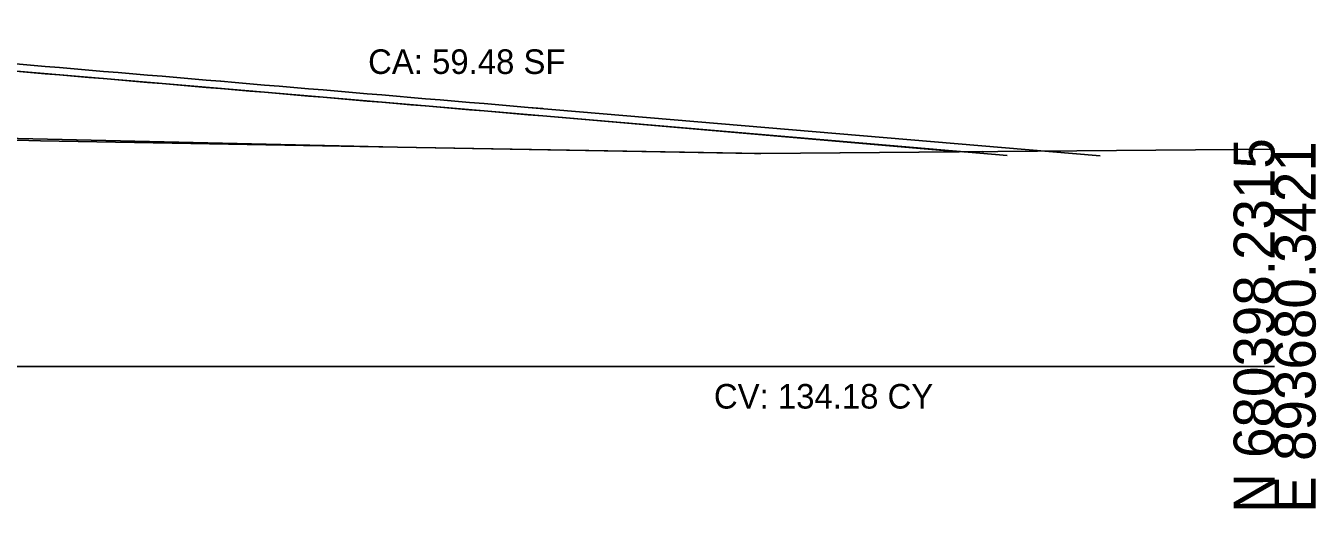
# Model space of a CAD drawing. Extents: x -26 to 4303, y -13 to 10775.
# Drawn here: x 1214.7 to 1302.8, y 490.3 to 523.3 of the extents above; entities that cross this region are included whole.
import ezdxf

# ---------------------------------------------------------------- set-up
doc = ezdxf.new("R2010")
doc.units = 0
for name, color, linetype in [('DTM_P_FINISHED_GRADE', 7, 'Continuous'), ('DTM_X_GROUND', 7, 'Continuous'), ('X_PROFILES_1', 7, 'Continuous'), ('XS_CELL', 7, 'Continuous'), ('XS_M_SHAPES_EARTHWORK', 7, 'Continuous'), ('XS_P_DR_GRAVEL', 7, 'Continuous'), ('XS_SHEET_EW_TX_AREA', 7, 'Continuous'), ('XS_SHEET_EW_TX_VOLUME', 7, 'Continuous')]:
    doc.layers.add(name, color=color, linetype=linetype)

msp = doc.modelspace()

# ---------------------------------------------------------------- linework, layer by layer
at = {"layer": 'DTM_P_FINISHED_GRADE'}
for p, q in [((1214.001, 520.688), (1215.001, 520.603)), ((1215.001, 520.603), (1216.001, 520.518)), ((1216.001, 520.518), (1216.001, 520.518)), ((1216.001, 520.518), (1217.001, 520.433)), ((1217.001, 520.433), (1217.001, 520.433)), ((1217.001, 520.433), (1218, 520.348)), ((1218, 520.348), (1218.001, 520.348)), ((1218.001, 520.348), (1218.001, 520.348)), ((1218.001, 520.348), (1219.001, 520.263)), ((1219.001, 520.263), (1219.001, 520.263)), ((1219.001, 520.263), (1220.001, 520.178)), ((1220.001, 520.178), (1220.001, 520.178)), ((1220.001, 520.178), (1221.001, 520.093)), ((1221.001, 520.093), (1221.001, 520.093)), ((1221.001, 520.093), (1222.001, 520.008)), ((1222.001, 520.008), (1223, 519.923)), ((1223, 519.923), (1223.001, 519.923)), ((1223.001, 519.923), (1223.001, 519.923)), ((1223.001, 519.923), (1224.001, 519.838)), ((1224.001, 519.838), (1224.001, 519.838)), ((1224.001, 519.838), (1225.001, 519.753)), ((1225.001, 519.753), (1225.001, 519.753)), ((1225.001, 519.753), (1226.001, 519.668)), ((1226.001, 519.668), (1227.001, 519.583)), ((1227.001, 519.583), (1227.001, 519.583)), ((1227.001, 519.583), (1228, 519.498)), ((1228, 519.498), (1228.001, 519.498)), ((1228.001, 519.498), (1228.001, 519.498)), ((1228.001, 519.498), (1229.001, 519.413)), ((1229.001, 519.413), (1229.001, 519.413)), ((1229.001, 519.413), (1230.001, 519.328)), ((1230.001, 519.328), (1230.001, 519.328)), ((1230.001, 519.328), (1231.001, 519.243)), ((1231.001, 519.243), (1232.001, 519.158)), ((1232.001, 519.158), (1232.001, 519.158)), ((1232.001, 519.158), (1233, 519.073)), ((1233, 519.073), (1233.001, 519.073)), ((1233.001, 519.073), (1233.001, 519.073)), ((1233.001, 519.073), (1234.001, 518.988)), ((1234.001, 518.988), (1234.001, 518.988)), ((1234.001, 518.988), (1235.001, 518.903)), ((1235.001, 518.903), (1235.001, 518.903)), ((1235.001, 518.903), (1236.001, 518.818)), ((1236.001, 518.818), (1237.001, 518.733)), ((1237.001, 518.733), (1237.001, 518.733)), ((1237.001, 518.733), (1238, 518.648)), ((1238, 518.648), (1238.001, 518.648)), ((1238.001, 518.648), (1238.001, 518.648)), ((1238.001, 518.648), (1239.001, 518.563)), ((1239.001, 518.563), (1239.001, 518.563)), ((1239.001, 518.563), (1240.001, 518.478)), ((1240.001, 518.478), (1240.001, 518.478)), ((1240.001, 518.478), (1241.001, 518.393)), ((1241.001, 518.393), (1241.001, 518.393)), ((1241.001, 518.393), (1242.001, 518.308)), ((1242.001, 518.308), (1243, 518.223)), ((1243, 518.223), (1243.001, 518.223)), ((1243.001, 518.223), (1243.001, 518.223)), ((1243.001, 518.223), (1244.001, 518.138)), ((1244.001, 518.138), (1244.001, 518.138)), ((1244.001, 518.138), (1245.001, 518.053)), ((1245.001, 518.053), (1246.001, 517.968)), ((1246.001, 517.968), (1246.001, 517.968)), ((1246.001, 517.968), (1247.001, 517.883)), ((1247.001, 517.883), (1247.001, 517.883)), ((1247.001, 517.883), (1248, 517.798)), ((1248, 517.798), (1248.001, 517.798)), ((1248.001, 517.798), (1248.001, 517.798)), ((1248.001, 517.798), (1249.001, 517.713)), ((1249.001, 517.713), (1249.001, 517.713)), ((1249.001, 517.713), (1250.001, 517.628)), ((1250.001, 517.628), (1250.001, 517.628))]:
    msp.add_line(p, q, dxfattribs=at)
at = {"layer": 'DTM_X_GROUND'}
msp.add_lwpolyline([(1101.628, 516.588), (1147.172, 516.668), (1150.012, 516.67), (1150.055, 516.671), (1152.579, 516.678), (1170.486, 516.729), (1170.82, 516.733), (1172.748, 516.665), (1215.691, 515.416), (1264.465, 514.566), (1264.666, 514.565), (1264.909, 514.564), (1300, 514.85)], dxfattribs=at)
at = {"layer": 'XS_CELL'}
msp.add_line((1150, 500), (1300, 500), dxfattribs=at)
at = {"layer": 'XS_P_DR_GRAVEL'}
for p, q in [((1215.001, 520.603), (1214.001, 520.688)), ((1216.001, 520.518), (1215.001, 520.603)), ((1217.001, 520.433), (1216.001, 520.518)), ((1216.001, 520.518), (1216.001, 520.518)), ((1218, 520.348), (1217.001, 520.433)), ((1217.001, 520.433), (1217.001, 520.433)), ((1218.001, 520.348), (1218, 520.348)), ((1219.001, 520.263), (1218.001, 520.348)), ((1218.001, 520.348), (1218.001, 520.348)), ((1220.001, 520.178), (1219.001, 520.263)), ((1219.001, 520.263), (1219.001, 520.263)), ((1221.001, 520.093), (1220.001, 520.178)), ((1220.001, 520.178), (1220.001, 520.178)), ((1222.001, 520.008), (1221.001, 520.093)), ((1221.001, 520.093), (1221.001, 520.093)), ((1223, 519.923), (1222.001, 520.008)), ((1223.001, 519.923), (1223, 519.923)), ((1224.001, 519.838), (1223.001, 519.923)), ((1223.001, 519.923), (1223.001, 519.923)), ((1225.001, 519.753), (1224.001, 519.838)), ((1224.001, 519.838), (1224.001, 519.838)), ((1226.001, 519.668), (1225.001, 519.753)), ((1225.001, 519.753), (1225.001, 519.753)), ((1227.001, 519.583), (1226.001, 519.668)), ((1228, 519.498), (1227.001, 519.583)), ((1227.001, 519.583), (1227.001, 519.583)), ((1228.001, 519.498), (1228, 519.498)), ((1229.001, 519.413), (1228.001, 519.498)), ((1228.001, 519.498), (1228.001, 519.498)), ((1230.001, 519.328), (1229.001, 519.413)), ((1229.001, 519.413), (1229.001, 519.413)), ((1231.001, 519.243), (1230.001, 519.328)), ((1230.001, 519.328), (1230.001, 519.328)), ((1232.001, 519.158), (1231.001, 519.243)), ((1233, 519.073), (1232.001, 519.158)), ((1232.001, 519.158), (1232.001, 519.158)), ((1233.001, 519.073), (1233, 519.073)), ((1234.001, 518.988), (1233.001, 519.073)), ((1233.001, 519.073), (1233.001, 519.073)), ((1235.001, 518.903), (1234.001, 518.988)), ((1234.001, 518.988), (1234.001, 518.988)), ((1236.001, 518.818), (1235.001, 518.903)), ((1235.001, 518.903), (1235.001, 518.903)), ((1237.001, 518.733), (1236.001, 518.818)), ((1238, 518.648), (1237.001, 518.733)), ((1237.001, 518.733), (1237.001, 518.733)), ((1238.001, 518.648), (1238, 518.648)), ((1239.001, 518.563), (1238.001, 518.648)), ((1238.001, 518.648), (1238.001, 518.648)), ((1240.001, 518.478), (1239.001, 518.563)), ((1239.001, 518.563), (1239.001, 518.563)), ((1241.001, 518.393), (1240.001, 518.478)), ((1240.001, 518.478), (1240.001, 518.478)), ((1242.001, 518.308), (1241.001, 518.393)), ((1241.001, 518.393), (1241.001, 518.393)), ((1243, 518.223), (1242.001, 518.308)), ((1243.001, 518.223), (1243, 518.223)), ((1244.001, 518.138), (1243.001, 518.223)), ((1243.001, 518.223), (1243.001, 518.223)), ((1245.001, 518.053), (1244.001, 518.138)), ((1244.001, 518.138), (1244.001, 518.138)), ((1246.001, 517.968), (1245.001, 518.053)), ((1247.001, 517.883), (1246.001, 517.968)), ((1246.001, 517.968), (1246.001, 517.968)), ((1248, 517.798), (1247.001, 517.883)), ((1247.001, 517.883), (1247.001, 517.883)), ((1248.001, 517.798), (1248, 517.798)), ((1249.001, 517.713), (1248.001, 517.798)), ((1248.001, 517.798), (1248.001, 517.798)), ((1288.079, 514.392), (1249.001, 517.713)), ((1249.001, 517.713), (1249.001, 517.713))]:
    msp.add_line(p, q, dxfattribs=at)
msp.add_lwpolyline([(1214.001, 520.188), (1215.001, 520.103), (1216.001, 520.018), (1216.001, 520.018), (1217.001, 519.933), (1217.001, 519.933), (1218, 519.848), (1218.001, 519.848), (1218.001, 519.848), (1219.001, 519.763), (1219.001, 519.763), (1220.001, 519.678), (1220.001, 519.678), (1221.001, 519.593), (1221.001, 519.593), (1222.001, 519.508), (1223, 519.423), (1223.001, 519.423), (1223.001, 519.423), (1224.001, 519.338), (1224.001, 519.338), (1225.001, 519.253), (1225.001, 519.253), (1226.001, 519.168), (1227.001, 519.083), (1227.001, 519.083), (1228, 518.998), (1228.001, 518.998), (1228.001, 518.998), (1229.001, 518.913), (1229.001, 518.913), (1230.001, 518.828), (1230.001, 518.828), (1231.001, 518.743), (1232.001, 518.658), (1232.001, 518.658), (1233, 518.573), (1233.001, 518.573), (1233.001, 518.573), (1234.001, 518.488), (1234.001, 518.488), (1235.001, 518.403), (1235.001, 518.403), (1236.001, 518.318), (1237.001, 518.233), (1237.001, 518.233), (1238, 518.148), (1238.001, 518.148), (1238.001, 518.148), (1239.001, 518.063), (1239.001, 518.063), (1240.001, 517.978), (1240.001, 517.978), (1241.001, 517.893), (1241.001, 517.893), (1242.001, 517.808), (1243, 517.723), (1243.001, 517.723), (1243.001, 517.723), (1244.001, 517.638), (1244.001, 517.638), (1245.001, 517.553), (1246.001, 517.468), (1246.001, 517.468), (1247.001, 517.383), (1247.001, 517.383), (1248, 517.298), (1248.001, 517.298), (1248.001, 517.298), (1249.001, 517.213), (1249.001, 517.213), (1250.001, 517.128), (1281.734, 514.431)], dxfattribs=at)
at = {"layer": 'XS_SHEET_EW_TX_AREA'}
msp.add_lwpolyline([(1170.254, 523.292), (1180, 520.842), (1194.22, 516.04), (1240.078, 514.991), (1264.909, 514.564), (1278.437, 514.666), (1250.001, 517.128), (1227.501, 519.041), (1196.001, 521.718), (1183, 522.823), (1180.001, 523.078), (1177.001, 523.144)], close=True, dxfattribs=at)

# ---------------------------------------------------------------- texts
at = {"layer": 'X_PROFILES_1'}
for p in [(1278.655, 514.616), (1280.008, 514.627)]:
    msp.add_text('X', height=0.12, dxfattribs=at).set_placement(p)
at = {"layer": 'XS_CELL'}
for s, p in [('N 680398.2315', (1300, 490)), ('E 893680.3421', (1302.8, 490))]:
    msp.add_text(s, height=2.8, rotation=90, dxfattribs=at).set_placement(p)
at = {"layer": 'XS_M_SHAPES_EARTHWORK'}
msp.add_text('CV: 134.18 CY', height=1.68, dxfattribs=at).set_placement((1261.695, 497.12))
at = {"layer": 'XS_SHEET_EW_TX_VOLUME'}
msp.add_text('CA: 59.48 SF', height=1.68, dxfattribs=at).set_placement((1238.072, 520))

doc.saveas('drawing.dxf')
